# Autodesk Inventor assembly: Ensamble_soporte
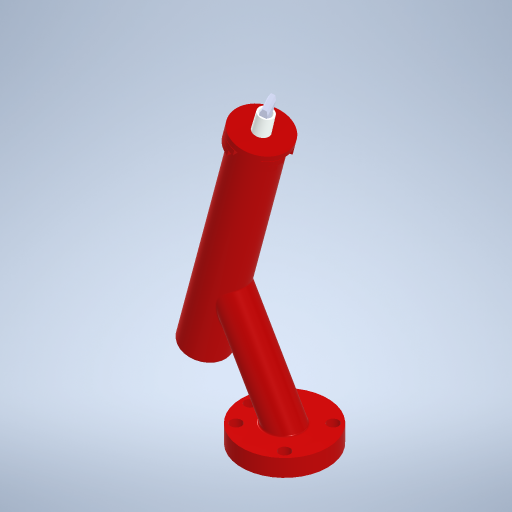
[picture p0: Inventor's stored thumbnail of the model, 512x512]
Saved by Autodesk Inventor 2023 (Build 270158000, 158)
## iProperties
Created: 2026-02
Part Number: Ensamble_soporte
Document SubType Name: Assembly
Designer: JULIAN
Author: JULIAN
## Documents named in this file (4)
- C:\Users\JULIAN\Desktop\Materias UN\Robótica\Laboratorio\Laboratorio 1\Herramienta_V3\Ensamble_soporte.iam
- C:\Users\JULIAN\Desktop\Materias UN\Robótica\Laboratorio\Laboratorio 1\Herramienta_V3\Base.ipt
- C:\Users\JULIAN\Desktop\Materias UN\Robótica\Laboratorio\Laboratorio 1\Herramienta_V3\Tapa.ipt
- C:\Users\JULIAN\Desktop\Materias UN\Robótica\Laboratorio\Laboratorio 1\Herramienta_V3\Marcador.ipt
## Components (3 placed, 3 different names)
1. Base:1 — Coincidencia:1, Coincidencia:2, Coincidencia:3, Coincidencia:4, Coincidencia:5
2. Tapa:1 — Coincidencia:3, Coincidencia:4, Coincidencia:5
3. Marcador:1 — Coincidencia:1, Coincidencia:2
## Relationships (5: Mate 5)
- Coincidencia:1 [Mate]: Base:1 ↔ Marcador:1
- Coincidencia:2 [Mate]: Base:1 ↔ Marcador:1
- Coincidencia:3 [Mate]: Base:1 ↔ Tapa:1
- Coincidencia:4 [Mate]: Base:1 ↔ Tapa:1
- Coincidencia:5 [Mate]: Base:1 ↔ Tapa:1
